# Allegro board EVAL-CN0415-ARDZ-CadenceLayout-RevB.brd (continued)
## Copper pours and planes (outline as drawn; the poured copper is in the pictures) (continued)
AGND on L2_GND: 48.01,0.89 48.01,5.87 44.83,5.87 44.83,11.68 43.69,11.68 43.69,35.05 51.18,35.05 53.47,37.34 53.47,40 54.74,41.27 54.74,50.29 52.83,50.29 52.83,52.7 105.28,52.7 105.28,50.67 107.19,50.67 107.19,2.92 104.78,2.92 104.78,0.89
PGND on TOP: 34.93,0.89 34.93,52.7 52.07,52.7 52.07,49.53 53.98,49.53 53.98,42.16 52.7,42.16 52.7,38.1 50.42,35.81 43.31,35.81 43.31,38.23 40.77,38.23 40.77,32.77 42.93,32.77 42.93,10.92 44.7,10.92 44.7,5.31 47.88,5.31 47.88,0.89 ; 4 cut-outs
PGND on BOTTOM: 34.93,0.89 34.93,50.67 37.08,50.67 37.08,52.7 52.07,52.7 52.07,49.53 53.98,49.53 53.98,42.16 52.7,42.16 52.7,35.81 42.93,35.81 42.93,10.92 44.7,10.92 44.7,5.28 47.88,5.28 47.88,0.89 ; 1 cut-out
PGND on L2_GND: 34.93,0.89 34.93,50.67 37.08,50.67 37.08,52.7 52.07,52.7 52.07,49.53 53.98,49.53 53.98,41.66 52.7,40.39 52.7,37.85 50.67,35.81 42.93,35.81 42.93,10.92 44.07,10.92 44.07,5.21 46.86,5.21 46.86,0.89
VCC on L3_PWR: 84.45,1.4 84.45,16.76 88.77,16.76 88.77,31.75 72.77,31.75 72.77,41.4 60.45,41.4 58.17,39.12 58.17,21.84 43.69,21.84 43.69,34.67 49.53,34.67 53.47,38.61 53.47,41.4 54.74,42.67 54.74,50.29 52.83,50.29 52.83,52.07 105.28,52.19 105.28,50.67 106.68,50.67 106.68,2.92 104.78,2.92 104.78,1.4 ; 1 cut-out
VIN on L3_PWR: 43.69,20.57 62.61,20.57 62.61,6.86 43.69,6.86
FET_DRIVER_OUTPUT on TOP: 48.51,45.08 53.98,45.08 53.98,43.43 52.7,42.16 52.7,38.1 52.07,37.46 48.51,37.46
RSENSE_N on TOP: 34.92,30.1 34.92,36.07 36.96,36.07 36.96,37.85 35.18,37.85 35.18,50.67 37.08,50.67 37.08,52.7 46.99,52.7 46.99,38.35 41.15,38.35 41.15,34.67 40.26,34.67 40.26,30.1
RSENSE_P on TOP: 34.95,14.94 34.95,28.83 40.26,28.83 40.26,14.94
SW_H_LT3433 on TOP: 64.64,18.67 72.64,18.67 72.64,27.18 68.71,27.18 68.71,21.84 64.64,21.84
UNNAMED_4_CN2P_I185_N1 on L3_PWR: 35.43,1.4 35.43,50.67 37.08,50.67 37.08,52.07 52.07,52.07 52.07,49.53 53.98,49.53 53.98,43.43 52.7,42.16 52.7,39.37 48.51,35.18 42.93,35.18 42.93,5.71 47.88,5.71 47.88,1.4
UNNAMED_6_DIOSCHOTTKY_I22_P on TOP: 73.41,27.18 77.34,27.18 77.34,22.48 80.9,22.48 80.9,18.8 73.41,18.8
VOUT_LT3433 on TOP: 77.04,11.81 77.04,12.4 77.17,12.4 77.85,13.08 77.85,15.49 74.3,15.49 74.3,18.29 84.58,18.29 84.58,13.21 78.61,13.21 78.61,11.84 78.56,11.84 78.56,11.81
VOUT_LT3433 on L3_PWR: 75.31,1.4 75.31,30.48 87.5,30.48 87.5,18.03 83.19,18.03 83.19,1.4
VOUT_LTC4367 on L3_PWR: 49.15,1.4 49.15,5.71 63.88,5.71 63.88,21.84 59.44,21.84 59.44,39.37 60.45,40.39 71.75,40.39 71.75,30.48 74.42,30.48 74.42,1.4

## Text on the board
Ref Des/Silkscreen Bottom: 08-048503 REV B Z | EVAL-CN0415-ARDZ
User.Comments: CR_Q_2 | CR_Q_3 | 1 | 2 | 3 | WIRE HOLES ENTRY | 6.   SOLDER PIN 2 TO PIN 3 OF JP1, JP2 | 8.   ATTACHED M029337 TO THE PIN 1&2 OF COMPONENTS P2 & P34. | 5.   SOLDER PIN 1 TO PIN 2 OF JP3, JP5, JP6, JP7, JP8 | 4.    DO NOT TRIM EXCESS LEADS OF P3, P4, P5, P6 & P7 | 7.   SOLDER PIN 1 TO PIN 2 OF P10, P16, P17, P18, P19, P20, P22, P23, P24, P25, P28, P29, P30, P31, P32 | PIN SHORT SOLDER DETAIL | VIEW FROM PRIMARY SIDE | SCALE 1:3 | JP## | P##
Ref Des/Silkscreen Top: VIN | RSENSE | ACTUATOR | 08-048503 REV B Z
PAGE_OUTLINE: 05APR18 | N/A | B | AS PER ECR-078923 | 30JUL18 | E.REYTA | EVAL-CN0415-ARDZ | CUSTOMER EVAL Z
DIMENSION: (REF) | DIA MAX
User.17: L2 GND | 08-      -07
User.18: L3 PWR | 08-      -08
User.45: FIGURE | SIZE | 10.0 | 20.0 | 45.0 | 50.0 | 125.0 | PLATED | NON-PLATED | FINISHED HOLES IN MILS | ALL UNITS ARE IN MILS | QTY | 23 | 233 | 2 | 50 | 4 | TOLERANCE/NOTES
